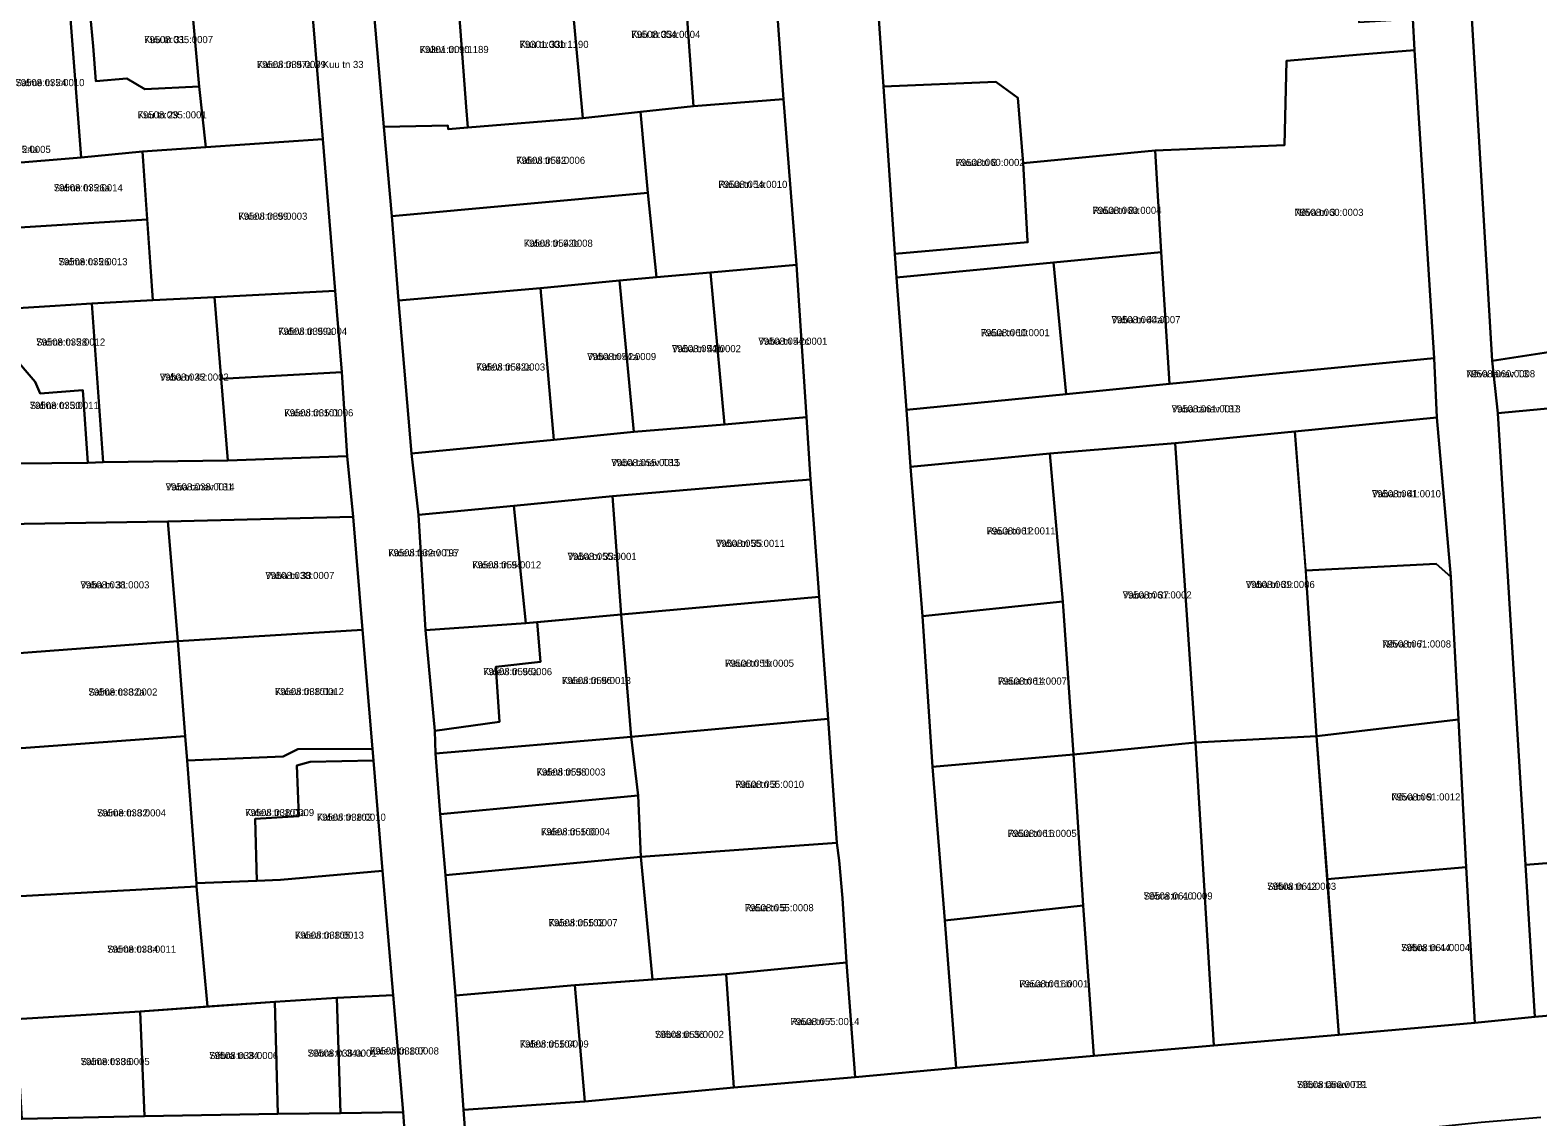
# Model space of a CAD drawing. Extents: x 643847 to 663718, y 6468443 to 6482775.
# Drawn here: x 659921 to 660238, y 6472605.6 to 6472833.9 of the extents above; entities that cross this region are included whole.
import ezdxf

# ---------------------------------------------------------------- set-up
doc = ezdxf.new("R2010")
doc.units = 0
for name, color, linetype in [('L_AADRESS', 7, 'Continuous'), ('PIIR', 7, 'Continuous'), ('TUNNUS', 7, 'Continuous')]:
    doc.layers.add(name, color=color, linetype=linetype)

msp = doc.modelspace()

# ---------------------------------------------------------------- linework, layer by layer
at = {"layer": 'PIIR'}
for points in [[(660203.35, 6472863.21), (660208.46, 6472861.98), (660210.69, 6472858.39), (660211, 6472851.61), (660199.47, 6472850.82), (660200.14, 6472838.93), (660200.33, 6472835.64), (660211.72, 6472836.33), (660212.02, 6472829.76), (660200.71, 6472828.81), (660185.11, 6472827.49), (660184.69, 6472809.8), (660157.5, 6472808.65), (660129.76, 6472806), (660128.66, 6472819.71), (660124.06, 6472823.05), (660100.43, 6472822.11), (660098.14, 6472855.63)], [(660211, 6472851.61), (660210.69, 6472858.39), (660208.46, 6472861.98), (660222.89, 6472863.66), (660223.54, 6472845.93), (660228.37, 6472764.43), (660229.55, 6472753.46), (660235.37, 6472658.55), (660237.34, 6472626.58), (660224.75, 6472625.33), (660222.93, 6472658.01), (660221.29, 6472689.07), (660219.71, 6472719.02), (660216.75, 6472752.52), (660216.15, 6472765.02), (660212.02, 6472829.76), (660211.72, 6472836.33)], [(660077.17, 6472850.51), (660079.41, 6472819.41), (660060.47, 6472817.98), (660058.23, 6472848.98)], [(660010.66, 6472845.02), (660034.34, 6472846.85), (660037.19, 6472815.46), (660013.03, 6472813.46), (660012.7, 6472817.8)], [(660058.23, 6472848.98), (660060.47, 6472817.98), (660049.32, 6472816.79), (660037.19, 6472815.46), (660034.34, 6472846.85)], [(660223.54, 6472845.93), (660252.63, 6472847.23), (660252.87, 6472844.23), (660252.99, 6472842.3), (660280.1, 6472844.11), (660283.18, 6472797.44), (660257.75, 6472796.09), (660259.35, 6472769.21), (660228.37, 6472764.43)], [(659992.81, 6472843.71), (660010.66, 6472845.02), (660012.7, 6472817.8), (660013.03, 6472813.46), (660008.9, 6472813.11), (660008.83, 6472813.92), (659995.36, 6472813.65)], [(659954.88, 6472840.89), (659956.57, 6472822.09), (659945.16, 6472821.52), (659941.36, 6472823.78), (659934.83, 6472823.24), (659934.27, 6472830.57), (659933.44, 6472839.52)], [(659969.2, 6472841.91), (659979.99, 6472842.56), (659982.55, 6472811.02), (659957.99, 6472809.36), (659956.57, 6472822.09), (659954.88, 6472840.89)], [(659904.14, 6472837.44), (659929.28, 6472839.05), (659931.75, 6472807.15), (659915.69, 6472805.84), (659915.26, 6472810.72), (659906.1, 6472810.12)], [(659933.44, 6472839.52), (659934.27, 6472830.57), (659934.83, 6472823.24), (659941.36, 6472823.78), (659945.16, 6472821.52), (659956.57, 6472822.09), (659957.99, 6472809.36), (659944.66, 6472808.45), (659931.75, 6472807.15), (659929.28, 6472839.05)], [(660160.52, 6472759.62), (660158.82, 6472787.29), (660157.5, 6472808.65), (660184.69, 6472809.8), (660185.11, 6472827.49), (660200.71, 6472828.81), (660212.02, 6472829.76), (660216.15, 6472765.02)], [(660100.43, 6472822.11), (660124.06, 6472823.05), (660128.66, 6472819.71), (660129.76, 6472806), (660130.72, 6472789.63), (660130.74, 6472789.38), (660102.83, 6472786.95)], [(660082.11, 6472784.63), (660064.04, 6472783.04), (660052.71, 6472782.03), (660050.9, 6472799.72), (660050.18, 6472807.49), (660049.32, 6472816.79), (660060.47, 6472817.98), (660079.41, 6472819.41)], [(660050.9, 6472799.72), (659997.05, 6472794.88), (659995.36, 6472813.65), (660008.83, 6472813.92), (660008.9, 6472813.11), (660013.03, 6472813.46), (660037.19, 6472815.46), (660049.32, 6472816.79), (660050.18, 6472807.49)], [(659985.15, 6472779.15), (659959.78, 6472777.85), (659946.85, 6472777.16), (659944.66, 6472808.45), (659957.99, 6472809.36), (659982.55, 6472811.02)], [(659907.25, 6472791.7), (659906.45, 6472805.55), (659915.69, 6472805.84), (659931.75, 6472807.15), (659944.66, 6472808.45), (659945.66, 6472794.17), (659917.7, 6472792.37)], [(660102.83, 6472786.95), (660130.74, 6472789.38), (660130.72, 6472789.63), (660129.76, 6472806), (660157.5, 6472808.65), (660158.82, 6472787.29), (660136.16, 6472785.12), (660103.17, 6472781.98)], [(659997.05, 6472794.88), (660050.9, 6472799.72), (660052.71, 6472782.03), (660044.9, 6472781.32), (660028.32, 6472779.69), (659998.46, 6472777.11)], [(659908.23, 6472774.88), (659907.25, 6472791.7), (659917.7, 6472792.37), (659945.66, 6472794.17), (659946.85, 6472777.16), (659933.99, 6472776.51), (659925.2, 6472775.96)], [(660160.52, 6472759.62), (660138.79, 6472757.46), (660136.16, 6472785.12), (660158.82, 6472787.29)], [(660067.01, 6472751.09), (660064.04, 6472783.04), (660082.11, 6472784.63), (660084.21, 6472752.59)], [(660103.17, 6472781.98), (660136.16, 6472785.12), (660138.79, 6472757.46), (660105.25, 6472754.12)], [(660031.11, 6472747.83), (660028.32, 6472779.69), (660044.9, 6472781.32), (660047.94, 6472749.54)], [(660044.9, 6472781.32), (660052.71, 6472782.03), (660064.04, 6472783.04), (660067.01, 6472751.09), (660047.94, 6472749.54)], [(659936.39, 6472743.16), (659933.99, 6472776.51), (659946.85, 6472777.16), (659959.78, 6472777.85), (659961.17, 6472760.66), (659962.56, 6472743.53)], [(659986.55, 6472762.03), (659961.17, 6472760.66), (659959.78, 6472777.85), (659985.15, 6472779.15)], [(660031.11, 6472747.83), (660001.23, 6472744.99), (659998.46, 6472777.11), (660028.32, 6472779.69)], [(659908.23, 6472774.88), (659925.2, 6472775.96), (659933.99, 6472776.51), (659936.39, 6472743.16), (659933.18, 6472743.02), (659932.08, 6472758.31), (659923.13, 6472757.59), (659922.1, 6472760), (659917.08, 6472765.87), (659908.85, 6472765.34)], [(660229.55, 6472753.46), (660228.37, 6472764.43), (660259.35, 6472769.21), (660284.9, 6472771.51), (660291.88, 6472772.1), (660322.5, 6472773.87), (660325.3, 6472762.42), (660271.56, 6472757.4)], [(659933.18, 6472743.02), (659910.3, 6472742.78), (659908.85, 6472765.34), (659917.08, 6472765.87), (659922.1, 6472760), (659923.13, 6472757.59), (659932.08, 6472758.31)], [(660135.39, 6472745), (660106.08, 6472742.17), (660105.25, 6472754.12), (660138.79, 6472757.46), (660160.52, 6472759.62), (660216.15, 6472765.02), (660216.75, 6472752.52), (660186.87, 6472749.62), (660161.72, 6472747.16)], [(659987.66, 6472744.39), (659962.56, 6472743.53), (659961.17, 6472760.66), (659986.55, 6472762.03)], [(660229.55, 6472753.46), (660271.56, 6472757.4), (660274.37, 6472696.09), (660274.51, 6472692.98), (660268.86, 6472692.36), (660261.66, 6472691.59), (660262.68, 6472672.26), (660263.28, 6472660.72), (660235.37, 6472658.55)], [(660022.74, 6472733.99), (660002.7, 6472732.06), (660001.23, 6472744.99), (660031.11, 6472747.83), (660047.94, 6472749.54), (660067.01, 6472751.09), (660084.21, 6472752.59), (660085.05, 6472739.54), (660076.56, 6472738.82), (660043.44, 6472736.02)], [(660186.87, 6472749.62), (660216.75, 6472752.52), (660219.71, 6472719.02), (660216.61, 6472721.76), (660189.17, 6472720.4)], [(660186.87, 6472749.62), (660189.37, 6472717.88), (660191.44, 6472685.6), (660166.01, 6472684.21), (660161.72, 6472747.16)], [(660161.72, 6472747.16), (660166.01, 6472684.21), (660140.35, 6472681.75), (660138.09, 6472713.84), (660135.39, 6472745)], [(659911.12, 6472730.04), (659910.3, 6472742.78), (659933.18, 6472743.02), (659936.39, 6472743.16), (659962.56, 6472743.53), (659987.66, 6472744.39), (659988.93, 6472731.66), (659949.97, 6472730.68)], [(660108.63, 6472710.8), (660106.08, 6472742.17), (660135.39, 6472745), (660138.09, 6472713.84)], [(660076.56, 6472738.82), (660085.05, 6472739.54), (660085.68, 6472731.13), (660086.9, 6472714.88), (660045.3, 6472711.14), (660043.44, 6472736.02)], [(660043.44, 6472736.02), (660045.3, 6472711.14), (660025.21, 6472709.29), (660022.74, 6472733.99)], [(660004.15, 6472707.86), (660002.7, 6472732.06), (660022.74, 6472733.99), (660025.21, 6472709.29)], [(659949.97, 6472730.68), (659952.05, 6472705.52), (659913.07, 6472702.56), (659911.12, 6472730.04)], [(659988.93, 6472731.66), (659990.87, 6472707.92), (659952.05, 6472705.52), (659949.97, 6472730.68)], [(660191.44, 6472685.6), (660189.37, 6472717.88), (660189.17, 6472720.4), (660216.61, 6472721.76), (660219.71, 6472719.02), (660221.29, 6472689.07)], [(660088.8, 6472689.2), (660047.41, 6472685.42), (660045.3, 6472711.14), (660086.9, 6472714.88)], [(660108.63, 6472710.8), (660138.09, 6472713.84), (660140.35, 6472681.75), (660110.69, 6472679.14)], [(660006.24, 6472681.9), (660006.12, 6472686.71), (660019.69, 6472688.56), (660018.91, 6472700.12), (660028.35, 6472701.2), (660027.59, 6472709.51), (660045.3, 6472711.14), (660047.41, 6472685.42)], [(659990.87, 6472707.92), (659993.01, 6472682.89), (659977.3, 6472682.86), (659974.24, 6472681.3), (659954.02, 6472680.47), (659953.63, 6472685.58), (659952.05, 6472705.52)], [(660004.15, 6472707.86), (660025.21, 6472709.29), (660027.59, 6472709.51), (660028.35, 6472701.2), (660018.91, 6472700.12), (660019.69, 6472688.56), (660006.12, 6472686.71)], [(659913.07, 6472702.56), (659952.05, 6472705.52), (659953.63, 6472685.58), (659914.34, 6472682.67)], [(660090.59, 6472663.14), (660049.44, 6472660.19), (660048.84, 6472673.08), (660047.41, 6472685.42), (660088.8, 6472689.2)], [(660191.44, 6472685.6), (660221.29, 6472689.07), (660222.93, 6472658.01), (660193.7, 6472655.52)], [(659914.34, 6472682.67), (659953.63, 6472685.58), (659954.02, 6472680.47), (659955.99, 6472654.65), (659956.03, 6472654.01), (659916.39, 6472651.82)], [(660006.24, 6472681.9), (660047.41, 6472685.42), (660048.84, 6472673.08), (660007.24, 6472669.15)], [(660169.85, 6472620.58), (660166.01, 6472684.21), (660191.44, 6472685.6), (660193.82, 6472654.4), (660196.13, 6472622.77)], [(659993.21, 6472680.44), (659979.92, 6472680.19), (659977.12, 6472679.42), (659977.55, 6472668.73), (659968.33, 6472668.18), (659968.68, 6472655.15), (659955.99, 6472654.65), (659954.02, 6472680.47), (659974.24, 6472681.3), (659977.3, 6472682.86), (659993.01, 6472682.89)], [(660144.64, 6472618.42), (660142.37, 6472649.98), (660140.35, 6472681.75), (660166.01, 6472684.21), (660169.85, 6472620.58)], [(659995.12, 6472657.26), (659973.68, 6472655.35), (659968.68, 6472655.15), (659968.33, 6472668.18), (659977.55, 6472668.73), (659977.12, 6472679.42), (659979.92, 6472680.19), (659993.21, 6472680.44)], [(660110.69, 6472679.14), (660140.35, 6472681.75), (660142.37, 6472649.98), (660113.3, 6472646.81)], [(660007.24, 6472669.15), (660048.84, 6472673.08), (660049.44, 6472660.19), (660008.37, 6472656.38)], [(660091.13, 6472659.42), (660091.83, 6472651.52), (660092.63, 6472637.99), (660067.32, 6472635.52), (660051.85, 6472634.4), (660049.44, 6472660.19), (660090.59, 6472663.14)], [(660008.37, 6472656.38), (660049.44, 6472660.19), (660051.85, 6472634.4), (660035.56, 6472633.23), (660010.47, 6472631.05)], [(660237.34, 6472626.58), (660235.37, 6472658.55), (660263.28, 6472660.72), (660264.93, 6472629.04)], [(659995.12, 6472657.26), (659997.38, 6472631.15), (659985.5, 6472630.55), (659972.46, 6472629.74), (659958.34, 6472628.73), (659956.03, 6472654.01), (659955.99, 6472654.65), (659968.68, 6472655.15), (659973.68, 6472655.35)], [(660193.7, 6472655.52), (660222.93, 6472658.01), (660224.75, 6472625.33), (660196.13, 6472622.77)], [(659916.39, 6472651.82), (659956.03, 6472654.01), (659958.34, 6472628.73), (659944.16, 6472627.74), (659918.08, 6472626.11)], [(660115.71, 6472615.88), (660113.3, 6472646.81), (660142.37, 6472649.98), (660144.64, 6472618.42)], [(660068.99, 6472611.72), (660067.32, 6472635.52), (660092.63, 6472637.99), (660094.5, 6472613.92)], [(660037.65, 6472608.76), (660035.56, 6472633.23), (660067.32, 6472635.52), (660068.99, 6472611.72)], [(660010.47, 6472631.05), (660035.56, 6472633.23), (660037.65, 6472608.76), (660012.12, 6472607.03)], [(659945.04, 6472605.68), (659944.16, 6472627.74), (659972.46, 6472629.74), (659973.07, 6472606.17)], [(659973.07, 6472606.17), (659972.46, 6472629.74), (659985.5, 6472630.55), (659986.28, 6472606.35)], [(659999.43, 6472606.53), (659986.28, 6472606.35), (659985.5, 6472630.55), (659997.38, 6472631.15)], [(659919.39, 6472605.15), (659918.08, 6472626.11), (659944.16, 6472627.74), (659945.04, 6472605.68)], [(659876.89, 6472583.38), (659844.75, 6472583.46), (659843.03, 6472604.06), (659874.72, 6472604.82), (659906.44, 6472605.05), (659919.39, 6472605.15), (659945.04, 6472605.68), (659973.07, 6472606.17), (659986.28, 6472606.35), (659999.43, 6472606.53), (660001.06, 6472584), (659999.66, 6472585.31), (659998.34, 6472585.83), (659975.93, 6472585), (659945.57, 6472584.07), (659937.8, 6472584.46), (659929.15, 6472584.26), (659920.54, 6472584.03), (659907.78, 6472583.92)]]:
    msp.add_lwpolyline(points, close=True, dxfattribs=at)
for points in [[(660098.14, 6472855.63), (660100.43, 6472822.11), (660102.83, 6472786.95), (660103.17, 6472781.98), (660105.25, 6472754.12), (660106.08, 6472742.17), (660108.63, 6472710.8), (660110.69, 6472679.14), (660113.3, 6472646.81), (660115.71, 6472615.88), (660094.5, 6472613.92), (660092.63, 6472637.99), (660091.83, 6472651.52), (660091.13, 6472659.42), (660090.59, 6472663.14), (660088.8, 6472689.2), (660086.9, 6472714.88), (660085.68, 6472731.13), (660085.05, 6472739.54), (660084.21, 6472752.59), (660082.11, 6472784.63), (660079.41, 6472819.41), (660077.17, 6472850.51)], [(659992.81, 6472843.71), (659995.36, 6472813.65), (659997.05, 6472794.88), (659998.46, 6472777.11), (660001.23, 6472744.99), (660002.7, 6472732.06), (660004.15, 6472707.86), (660006.12, 6472686.71), (660006.24, 6472681.9), (660007.24, 6472669.15), (660008.37, 6472656.38), (660010.47, 6472631.05), (660012.12, 6472607.03), (660013.75, 6472585.2)], [(660001.06, 6472584), (659999.43, 6472606.53), (659997.38, 6472631.15), (659995.12, 6472657.26), (659993.21, 6472680.44), (659993.01, 6472682.89), (659990.87, 6472707.92), (659988.93, 6472731.66), (659987.66, 6472744.39), (659986.55, 6472762.03), (659985.15, 6472779.15), (659982.55, 6472811.02), (659979.99, 6472842.56)], [(660238.61, 6472605.46), (660226.03, 6472604.38), (660211.15, 6472602.84), (660197.15, 6472601.6), (660177.43, 6472599.8), (660146.13, 6472597.12), (660117.42, 6472594.56), (660095.87, 6472592.76), (660056.32, 6472589.1), (660013.75, 6472585.2), (660012.12, 6472607.03), (660037.65, 6472608.76), (660068.99, 6472611.72), (660094.5, 6472613.92), (660115.71, 6472615.88), (660144.64, 6472618.42), (660169.85, 6472620.58), (660196.13, 6472622.77), (660224.75, 6472625.33), (660237.34, 6472626.58), (660264.93, 6472629.04)]]:
    msp.add_lwpolyline(points, dxfattribs=at)

# ---------------------------------------------------------------- texts
at = {"layer": 'L_AADRESS'}
for s, p in [('Kuu tn 31', (659944.98, 6472831.21)), ('Kuu tn 33b', (660023.92, 6472830.2)), ('Kuu tn 33a', (660047.41, 6472832.3)), ('Kalevi tn 90', (660002.92, 6472829.13)), ('Kalevi tn 97a // Kuu tn 33', (659968.71, 6472825.98)), ('Salme tn 24', (659917.95, 6472822.17)), ('Kuu tn 29', (659943.64, 6472815.39)), ('Salme tn 24a', (659910.87, 6472808.13)), ('Kalevi tn 92', (660023.2, 6472805.83)), ('Raua tn 8', (660115.59, 6472805.39)), ('Salme tn 26a', (659926.01, 6472800.07)), ('Raua tn 1a', (660065.71, 6472800.78)), ('Raua tn 8a', (660144.36, 6472795.32)), ('Nõva tn 3', (660186.82, 6472794.9)), ('Kalevi tn 99', (659964.8, 6472794.09)), ('Kalevi tn 92b', (660024.81, 6472788.41)), ('Salme tn 26', (659927, 6472784.53)), ('Vaba tn 44a', (660148.34, 6472772.35)), ('Kalevi tn 99a', (659973.16, 6472769.9)), ('Raua tn 10', (660120.86, 6472769.62)), ('Salme tn 28', (659922.31, 6472767.64)), ('Vaba tn 42b', (660055.95, 6472766.26)), ('Vaba tn 42c', (660074.12, 6472767.82)), ('Vaba tn 42a', (660038.13, 6472764.6)), ('Vaba tn 42', (659948.28, 6472760.28)), ('Kalevi tn 92a', (660014.79, 6472762.4)), ('Nõva tänav T3', (660222.9, 6472760.98)), ('Salme tn 30', (659920.96, 6472754.33)), ('Vaba tänav T37', (660160.99, 6472753.6)), ('Kalevi tn 101', (659974.47, 6472752.78)), ('Vaba tänav T33', (660043.2, 6472742.32)), ('Vaba tänav T31', (659949.52, 6472737.21)), ('Vaba tn 41', (660203.1, 6472735.77)), ('Vaba tn 35', (660065.18, 6472725.34)), ('Raua tn 12', (660122.09, 6472727.95)), ('Kalevi tänav T97', (659996.3, 6472723.36)), ('Vaba tn 33a', (660034.02, 6472722.6)), ('Vaba tn 33', (659970.48, 6472718.59)), ('Kalevi tn 94', (660013.96, 6472720.83)), ('Vaba tn 31', (659931.6, 6472716.62)), ('Vaba tn 39', (660176.58, 6472716.7)), ('Vaba tn 37', (660150.7, 6472714.5)), ('Nõva tn 7', (660205.23, 6472704.2)), ('Raua tn 1b', (660067.1, 6472700.15)), ('Kalevi tn 96a', (660016.25, 6472698.39)), ('Kalevi tn 96', (660032.83, 6472696.52)), ('Raua tn 14', (660124.49, 6472696.4)), ('Salme tn 32a', (659933.28, 6472694.1)), ('Kalevi tn 101a', (659972.5, 6472694.2)), ('Kalevi tn 98', (660027.48, 6472677.29)), ('Raua tn 3', (660069.22, 6472674.7)), ('Nõva tn 9', (660207.18, 6472672.05)), ('Salme tn 32', (659935.09, 6472668.7)), ('Kalevi tn 103a', (659966.23, 6472668.77)), ('Kalevi tn 103', (659981.3, 6472667.79)), ('Kalevi tn 100', (660028.43, 6472664.73)), ('Raua tn 16', (660126.53, 6472664.39)), ('Sõbra tn 42', (660181.07, 6472653.27)), ('Sõbra tn 40', (660155.1, 6472651.24)), ('Kalevi tn 102', (660030.03, 6472645.62)), ('Raua tn 5', (660071.25, 6472648.77)), ('Kalevi tn 105', (659976.7, 6472643)), ('Salme tn 34', (659937.23, 6472640.06)), ('Sõbra tn 44', (660209.23, 6472640.39)), ('Raua tn 16b', (660128.97, 6472632.78)), ('Raua tn 7', (660080.86, 6472624.85)), ('Sõbra tn 36', (660052.38, 6472622.14)), ('Sõbra tn 34', (659958.67, 6472617.71)), ('Sõbra tn 34a', (659979.37, 6472618.21)), ('Kalevi tn 107', (659992.46, 6472618.67)), ('Kalevi tn 104', (660023.95, 6472620.13)), ('Salme tn 36', (659931.65, 6472616.44)), ('Sõbra tänav T31', (660187.34, 6472611.61))]:
    msp.add_text(s, height=1.5, dxfattribs=at).set_placement(p)
at = {"layer": 'TUNNUS'}
for s, p in [('79508:035:0007', (659944.98, 6472831.21)), ('79301:001:1190', (660023.92, 6472830.2)), ('79508:054:0004', (660047.41, 6472832.3)), ('79301:001:1189', (660002.92, 6472829.13)), ('79508:035:0009', (659968.71, 6472825.98)), ('79508:035:0010', (659917.95, 6472822.17)), ('79508:035:0001', (659943.64, 6472815.39)), ('79508:035:0005', (659910.87, 6472808.13)), ('79508:054:0006', (660023.2, 6472805.83)), ('79508:060:0002', (660115.59, 6472805.39)), ('79508:035:0014', (659926.01, 6472800.07)), ('79508:054:0010', (660065.71, 6472800.78)), ('79508:060:0004', (660144.36, 6472795.32)), ('79508:060:0003', (660186.82, 6472794.9)), ('79508:035:0003', (659964.8, 6472794.09)), ('79508:054:0008', (660024.81, 6472788.41)), ('79508:035:0013', (659927, 6472784.53)), ('79508:035:0004', (659973.16, 6472769.9)), ('79508:060:0001', (660120.86, 6472769.62)), ('79508:060:0007', (660148.34, 6472772.35)), ('79508:035:0012', (659922.31, 6472767.64)), ('79508:054:0002', (660055.95, 6472766.26)), ('79508:054:0001', (660074.12, 6472767.82)), ('79508:054:0009', (660038.13, 6472764.6)), ('79508:035:0002', (659948.28, 6472760.28)), ('79508:054:0003', (660014.79, 6472762.4)), ('79508:060:0008', (660222.9, 6472760.98)), ('79508:035:0011', (659920.96, 6472754.33)), ('79508:061:0013', (660160.99, 6472753.6)), ('79508:035:0006', (659974.47, 6472752.78)), ('79508:055:0015', (660043.2, 6472742.32)), ('79508:038:0014', (659949.52, 6472737.21)), ('79508:061:0010', (660203.1, 6472735.77)), ('79508:055:0011', (660065.18, 6472725.34)), ('79508:061:0011', (660122.09, 6472727.95)), ('79508:032:0016', (659996.3, 6472723.36)), ('79508:055:0001', (660034.02, 6472722.6)), ('79508:038:0007', (659970.48, 6472718.59)), ('79508:055:0012', (660013.96, 6472720.83)), ('79508:038:0003', (659931.6, 6472716.62)), ('79508:061:0006', (660176.58, 6472716.7)), ('79508:061:0002', (660150.7, 6472714.5)), ('79508:061:0008', (660205.23, 6472704.2)), ('79508:055:0005', (660067.1, 6472700.15)), ('79508:055:0006', (660016.25, 6472698.39)), ('79508:055:0013', (660032.83, 6472696.52)), ('79508:061:0007', (660124.49, 6472696.4)), ('79508:038:0002', (659933.28, 6472694.1)), ('79508:038:0012', (659972.5, 6472694.2)), ('79508:055:0003', (660027.48, 6472677.29)), ('79508:055:0010', (660069.22, 6472674.7)), ('79508:061:0012', (660207.18, 6472672.05)), ('79508:038:0004', (659935.09, 6472668.7)), ('79508:038:0009', (659966.23, 6472668.77)), ('79508:038:0010', (659981.3, 6472667.79)), ('79508:055:0004', (660028.43, 6472664.73)), ('79508:061:0005', (660126.53, 6472664.39)), ('79508:061:0003', (660181.07, 6472653.27)), ('79508:055:0008', (660071.25, 6472648.77)), ('79508:061:0009', (660155.1, 6472651.24)), ('79508:055:0007', (660030.03, 6472645.62)), ('79508:038:0013', (659976.7, 6472643)), ('79508:038:0011', (659937.23, 6472640.06)), ('79508:061:0004', (660209.23, 6472640.39)), ('79508:061:0001', (660128.97, 6472632.78)), ('79508:055:0014', (660080.86, 6472624.85)), ('79508:055:0002', (660052.38, 6472622.14)), ('79508:038:0006', (659958.67, 6472617.71)), ('79508:038:0001', (659979.37, 6472618.21)), ('79508:038:0008', (659992.46, 6472618.67)), ('79508:055:0009', (660023.95, 6472620.13)), ('79508:038:0005', (659931.65, 6472616.44)), ('79508:056:0019', (660187.34, 6472611.61))]:
    msp.add_text(s, height=1.5, dxfattribs=at).set_placement(p)

doc.saveas('drawing.dxf')
